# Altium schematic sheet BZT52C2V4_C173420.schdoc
size 127 x 101 mm
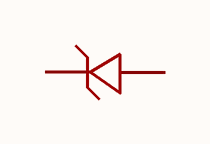
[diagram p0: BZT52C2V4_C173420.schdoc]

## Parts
D?  bzt52c2v4_c173420  [SOD-123FL_L2.7-W1.8-LS3.8-RD]  (value not drawn)

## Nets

Not connected (* = marked no-connect by the designer): D? 1(K) 2(A)

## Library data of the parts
D? = bzt52c2v4_c173420: 二极管配置:1个独立式;稳压值(标称值):2.4V;稳压值(范围):2.28V~2.52V;耗散功率(Pd):500mW;; Manufacturer: MDD(辰达半导体); AddInBom: yes; ModelId: 86f9151e155e4fe2af0c4f2e0a80302e; ModelName: SOD-123FL_L2.8-W1.8-H1.1-LS3.6; ModelTransform: 141.732,70.866,0,180,0,0,0,0,0; Diode Configuration: 1个独立式; Zener Voltage(Nom): 2.4V; Reverse Leakage Current (Ir): 120uA@1V; Pd - Power Dissipation: 500mW; Impedance(Zzt): 100Ω; Tolerance: ±5%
